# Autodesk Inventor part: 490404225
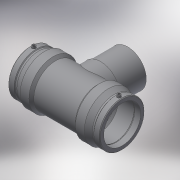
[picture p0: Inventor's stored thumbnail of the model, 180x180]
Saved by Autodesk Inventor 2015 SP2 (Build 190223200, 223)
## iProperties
Created: 2017-06
Part Number: 490404225
Material: Generic
Description: PLASSON TEE 225-225-225
Document SubType Name: Modeling
Designer: KIM
Mass: 12818 g
Surface Area: 10114.6 cm^2
Volume: 12818 cm^3
Density: 1 g/cm^3
Appearance: Default
Author: KIM
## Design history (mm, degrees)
derived "490404.ipt"
feature "Solid1::490404.ipt"
tag "TaggingFeature1"
body "Solid1"
other parameters: "d0" = 494, "d1" = 225, "d2" = 293, "d3" = 122, "d4" = 123.5, "d5" = 263.7, "d6" = 213.75, "d7" = 225, "d8" = 168 deg, "d10" = 48.8, "d11" = 16.26667, "d13" = 494, "d14" = 17.6296, "d17" = 202.5, "d18" = 225, "d19" = 3.52592, "d20" = 168 deg, "d22" = 272.49, "d23" = 293, "d24" = 264.3153, "d25" = 135 deg, "d26" = 345.8, "d27" = 135 deg, "d30" = 15, "d31" = 197.6, "d34" = 5 deg, "d35" = 15, "d39" = 5 deg, "d40" = 9.6, "d41" = 4.8, "d42" = 6, "d43" = 0, "d45" = 4, "d46" = 14, "d47" = 0, "d49" = 225, "d51" = 0, "d54" = 0, "d55" = 263.7, "d56" = 293, "d57" = 172.9, "d58" = 135 deg, "d59" = 122, "d60" = 122, "d61" = 135 deg, "d72" = 242.06, "d73" = 121.03, "d75" = 236.25, "d77" = 0, "d80" = 0, "d81" = 225, "d82" = 143.5, "d83" = 0, "d84" = 3, "d85" = 0, "d86" = 3, "d87" = 0, "d88" = 35.38, "d89" = 8.845, "d90" = 35.38, "d_" = 225, "L_" = 494, "L_1" = 122, "D_" = 293, "d_2" = 12
